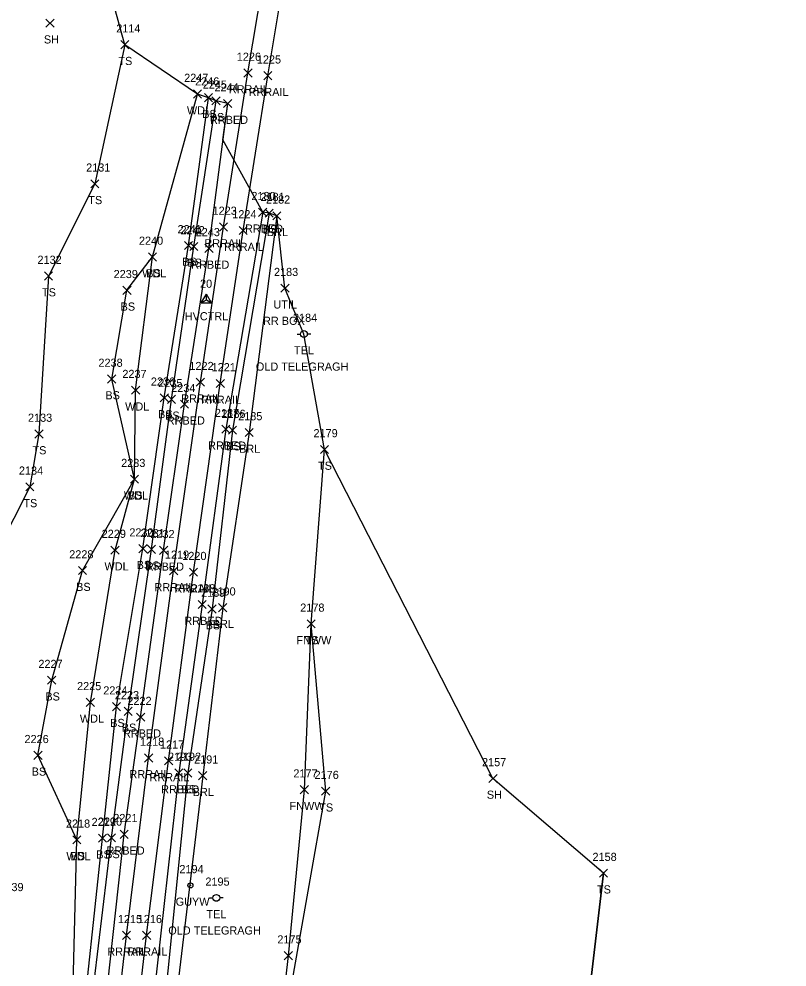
# Model space of a CAD drawing. Extents: x 1754529 to 1755810, y 621660 to 624656.
# Drawn here: x 1755616 to 1755804.8, y 623834.2 to 624067.2 of the extents above; entities that cross this region are included whole.
import ezdxf

# ---------------------------------------------------------------- set-up
doc = ezdxf.new("R2010")
doc.units = 0
for name, color, linetype in [('C_A', 7, 'Continuous'), ('C_I', 7, 'Continuous'), ('CPSM', 7, 'Continuous'), ('L_A', 7, 'Continuous'), ('L_I', 7, 'Continuous'), ('L_TIC', 7, 'Continuous'), ('LABL', 7, 'Continuous'), ('LAWA', 7, 'Continuous'), ('LELB', 7, 'Continuous'), ('LFNC', 7, 'Continuous'), ('LSOGP', 7, 'Continuous'), ('R_A', 7, 'Continuous'), ('R_I', 7, 'Continuous'), ('R_TIC', 7, 'Continuous'), ('RR', 7, 'Continuous'), ('RRB', 7, 'Continuous'), ('U_A', 7, 'Continuous'), ('U_C', 7, 'Continuous'), ('U_I', 7, 'Continuous'), ('UDEFAULT', 7, 'Continuous'), ('UP', 7, 'Continuous'), ('UPGW', 7, 'Continuous')]:
    doc.layers.add(name, color=color, linetype=linetype)

msp = doc.modelspace()

# ---------------------------------------------------------------- linework, layer by layer
at = {"layer": 'CPSM'}
for p, q in [((1755660.82, 623997.4), (1755662.07, 623999.57)), ((1755663.32, 623997.4), (1755662.07, 623999.57)), ((1755662.07, 623998.12), (1755662.07, 623999.57)), ((1755660.82, 623997.4), (1755662.07, 623998.12)), ((1755660.82, 623997.4), (1755663.32, 623997.4)), ((1755662.07, 623998.12), (1755662.07, 623998.12)), ((1755662.07, 623998.12), (1755663.32, 623997.4))]:
    msp.add_line(p, q, dxfattribs=at)
at = {"layer": 'L_TIC'}
for points in [[(1755622.67, 624065.15), (1755624.67, 624067.15)], [(1755624.67, 624065.15), (1755622.67, 624067.15)], [(1755641.06, 624059.86), (1755643.06, 624061.86)], [(1755643.06, 624059.86), (1755641.06, 624061.86)], [(1755658.88, 624047.72), (1755660.88, 624049.72)], [(1755660.88, 624047.72), (1755658.88, 624049.72)], [(1755661.62, 624046.83), (1755663.62, 624048.83)], [(1755663.62, 624046.83), (1755661.62, 624048.83)], [(1755663.45, 624046.05), (1755665.45, 624048.05)], [(1755665.45, 624046.05), (1755663.45, 624048.05)], [(1755633.66, 624025.67), (1755635.66, 624027.67)], [(1755635.66, 624025.67), (1755633.66, 624027.67)], [(1755676.5, 624018.45), (1755678.5, 624020.45)], [(1755678.5, 624018.45), (1755676.5, 624020.45)], [(1755678.41, 624017.81), (1755680.41, 624019.81)], [(1755680.41, 624017.81), (1755678.41, 624019.81)], [(1755656.7, 624010.52), (1755658.7, 624012.52)], [(1755658.7, 624010.52), (1755656.7, 624012.52)], [(1755657.98, 624010.28), (1755659.98, 624012.28)], [(1755659.98, 624010.28), (1755657.98, 624012.28)], [(1755647.86, 624007.69), (1755649.86, 624009.69)], [(1755649.86, 624007.69), (1755647.86, 624009.69)], [(1755647.86, 624007.69), (1755649.86, 624009.69)], [(1755649.86, 624007.69), (1755647.86, 624009.69)], [(1755622.28, 624003), (1755624.28, 624005)], [(1755624.28, 624003), (1755622.28, 624005)], [(1755641.56, 623999.5), (1755643.56, 624001.5)], [(1755643.56, 623999.5), (1755641.56, 624001.5)], [(1755637.82, 623977.7), (1755639.82, 623979.7)], [(1755639.82, 623977.7), (1755637.82, 623979.7)], [(1755643.69, 623974.95), (1755645.69, 623976.95)], [(1755645.69, 623974.95), (1755643.69, 623976.95)], [(1755650.75, 623973.07), (1755652.75, 623975.07)], [(1755652.75, 623973.07), (1755650.75, 623975.07)], [(1755652.51, 623972.7), (1755654.51, 623974.7)], [(1755654.51, 623972.7), (1755652.51, 623974.7)], [(1755667.5, 623965.15), (1755669.5, 623967.15)], [(1755669.5, 623965.15), (1755667.5, 623967.15)], [(1755671.58, 623964.56), (1755673.58, 623966.56)], [(1755673.58, 623964.56), (1755671.58, 623966.56)], [(1755619.94, 623964.19), (1755621.94, 623966.19)], [(1755621.94, 623964.19), (1755619.94, 623966.19)], [(1755690.1, 623960.39), (1755692.1, 623962.39)], [(1755692.1, 623960.39), (1755690.1, 623962.39)], [(1755643.4, 623953.08), (1755645.4, 623955.08)], [(1755645.4, 623953.08), (1755643.4, 623955.08)], [(1755643.4, 623953.08), (1755645.4, 623955.08)], [(1755645.4, 623953.08), (1755643.4, 623955.08)], [(1755617.71, 623951.2), (1755619.71, 623953.2)], [(1755619.71, 623951.2), (1755617.71, 623953.2)], [(1755638.63, 623935.66), (1755640.63, 623937.66)], [(1755640.63, 623935.66), (1755638.63, 623937.66)], [(1755645.5, 623936.01), (1755647.5, 623938.01)], [(1755647.5, 623936.01), (1755645.5, 623938.01)], [(1755647.59, 623935.85), (1755649.59, 623937.85)], [(1755649.59, 623935.85), (1755647.59, 623937.85)], [(1755630.64, 623930.62), (1755632.64, 623932.62)], [(1755632.64, 623930.62), (1755630.64, 623932.62)], [(1755662.47, 623921.18), (1755664.47, 623923.18)], [(1755664.47, 623921.18), (1755662.47, 623923.18)], [(1755665.1, 623921.5), (1755667.1, 623923.5)], [(1755667.1, 623921.5), (1755665.1, 623923.5)], [(1755686.83, 623917.52), (1755688.83, 623919.52)], [(1755688.83, 623917.52), (1755686.83, 623919.52)], [(1755686.83, 623917.52), (1755688.83, 623919.52)], [(1755688.83, 623917.52), (1755686.83, 623919.52)], [(1755623.07, 623903.69), (1755625.07, 623905.69)], [(1755625.07, 623903.69), (1755623.07, 623905.69)], [(1755632.57, 623898.24), (1755634.57, 623900.24)], [(1755634.57, 623898.24), (1755632.57, 623900.24)], [(1755639.01, 623897.18), (1755641.01, 623899.18)], [(1755641.01, 623897.18), (1755639.01, 623899.18)], [(1755641.85, 623896.02), (1755643.85, 623898.02)], [(1755643.85, 623896.02), (1755641.85, 623898.02)], [(1755619.7, 623885.23), (1755621.7, 623887.23)], [(1755621.7, 623885.23), (1755619.7, 623887.23)], [(1755656.52, 623880.88), (1755658.52, 623882.88)], [(1755658.52, 623880.88), (1755656.52, 623882.88)], [(1755660.18, 623880.21), (1755662.18, 623882.21)], [(1755662.18, 623880.21), (1755660.18, 623882.21)], [(1755731.5, 623879.55), (1755733.5, 623881.55)], [(1755733.5, 623879.55), (1755731.5, 623881.55)], [(1755685.15, 623876.78), (1755687.15, 623878.78)], [(1755687.15, 623876.78), (1755685.15, 623878.78)], [(1755690.4, 623876.41), (1755692.4, 623878.41)], [(1755692.4, 623876.41), (1755690.4, 623878.41)], [(1755629.26, 623864.45), (1755631.26, 623866.45)], [(1755631.26, 623864.45), (1755629.26, 623866.45)], [(1755629.26, 623864.45), (1755631.26, 623866.45)], [(1755631.26, 623864.45), (1755629.26, 623866.45)], [(1755635.58, 623864.85), (1755637.58, 623866.85)], [(1755637.58, 623864.85), (1755635.58, 623866.85)], [(1755637.78, 623864.94), (1755639.78, 623866.94)], [(1755639.78, 623864.94), (1755637.78, 623866.94)], [(1755758.64, 623856.27), (1755760.64, 623858.27)], [(1755760.64, 623856.27), (1755758.64, 623858.27)], [(1755681.22, 623835.98), (1755683.22, 623837.98)], [(1755683.22, 623835.98), (1755681.22, 623837.98)]]:
    msp.add_lwpolyline(points, dxfattribs=at)
at = {"layer": 'LABL'}
msp.add_lwpolyline([(1755679.41, 624018.81), (1755672.58, 623965.56), (1755666.1, 623922.5), (1755661.18, 623881.21), (1755654.48, 623825.24), (1755650.07, 623783.16), (1755645, 623731.12)], dxfattribs=at)
at = {"layer": 'LAWA'}
msp.add_lwpolyline([(1755619.86, 623730.16), (1755624.14, 623766.63), (1755628.98, 623813.62), (1755630.26, 623865.45), (1755633.57, 623899.24), (1755639.63, 623936.66), (1755644.4, 623954.08), (1755644.69, 623975.95), (1755648.86, 624008.69), (1755659.88, 624048.72)], dxfattribs=at)
at = {"layer": 'LELB'}
for points in [[(1755642.06, 624060.86), (1755634.66, 624026.67), (1755623.28, 624004), (1755620.94, 623965.19), (1755618.71, 623952.2), (1755606.81, 623928.84), (1755598.16, 623898.45), (1755598.5, 623876.91), (1755607.67, 623866.57), (1755613.91, 623849.85), (1755612.83, 623834.4)], [(1755621.92, 623730), (1755626.29, 623766.54), (1755630.92, 623812.95), (1755636.58, 623865.85), (1755640.01, 623898.18), (1755646.5, 623937.01), (1755651.75, 623974.07), (1755657.7, 624011.52), (1755662.62, 624047.83)], [(1755623.71, 623730.49), (1755627.77, 623766.25), (1755632.35, 623812.84), (1755638.78, 623865.94), (1755642.85, 623897.02), (1755648.59, 623936.85), (1755653.51, 623973.7), (1755658.98, 624011.28), (1755664.45, 624047.05)], [(1755677.5, 624019.45), (1755668.5, 623966.15), (1755663.47, 623922.18), (1755657.52, 623881.88), (1755651.77, 623825.19), (1755647.93, 623784.26), (1755642.72, 623732.01)], [(1755630.26, 623865.45), (1755620.7, 623886.23), (1755624.07, 623904.69), (1755631.64, 623931.62), (1755644.4, 623954.08), (1755638.82, 623978.7), (1755642.56, 624000.5), (1755648.86, 624008.69)], [(1755759.64, 623857.27), (1755754.21, 623811.35), (1755753.42, 623772.78), (1755766.33, 623740.32), (1755774.14, 623720.79), (1755758.9, 623706.26), (1755730.32, 623712.44), (1755693.64, 623709.04), (1755674.97, 623707.43), (1755670.91, 623711.42), (1755668.71, 623724.8), (1755675.07, 623772.54), (1755678.37, 623803.67), (1755691.4, 623877.41), (1755687.83, 623918.52), (1755691.1, 623961.39)]]:
    msp.add_lwpolyline(points, dxfattribs=at)
at = {"layer": 'LFNC'}
msp.add_lwpolyline([(1755678.37, 623803.67), (1755682.22, 623836.98), (1755686.15, 623877.78), (1755687.83, 623918.52)], dxfattribs=at)
at = {"layer": 'LSOGP'}
msp.add_lwpolyline([(1755754.21, 623811.35), (1755759.64, 623857.27), (1755732.5, 623880.55), (1755691.1, 623961.39), (1755686.05, 623989.75), (1755681.39, 624001.01), (1755679.41, 624018.81), (1755677.5, 624019.45), (1755675.92, 624019.67), (1755666.16, 624037.49), (1755667.32, 624046.39), (1755664.45, 624047.05), (1755662.62, 624047.83), (1755659.88, 624048.72), (1755642.06, 624060.86), (1755626.78, 624116.47)], dxfattribs=at)
at = {"layer": 'R_TIC'}
for points in [[(1755671.3, 624052.9), (1755673.3, 624054.9)], [(1755673.3, 624052.9), (1755671.3, 624054.9)], [(1755676.17, 624052.23), (1755678.17, 624054.23)], [(1755678.17, 624052.23), (1755676.17, 624054.23)], [(1755666.32, 624045.39), (1755668.32, 624047.39)], [(1755668.32, 624045.39), (1755666.32, 624047.39)], [(1755674.92, 624018.67), (1755676.92, 624020.67)], [(1755676.92, 624018.67), (1755674.92, 624020.67)], [(1755665.29, 624015.06), (1755667.29, 624017.06)], [(1755667.29, 624015.06), (1755665.29, 624017.06)], [(1755670.13, 624014.19), (1755672.13, 624016.19)], [(1755672.13, 624014.19), (1755670.13, 624016.19)], [(1755661.71, 624009.8), (1755663.71, 624011.8)], [(1755663.71, 624009.8), (1755661.71, 624011.8)], [(1755659.61, 623976.9), (1755661.61, 623978.9)], [(1755661.61, 623976.9), (1755659.61, 623978.9)], [(1755664.5, 623976.61), (1755666.5, 623978.61)], [(1755666.5, 623976.61), (1755664.5, 623978.61)], [(1755655.7, 623971.5), (1755657.7, 623973.5)], [(1755657.7, 623971.5), (1755655.7, 623973.5)], [(1755665.85, 623965.35), (1755667.85, 623967.35)], [(1755667.85, 623965.35), (1755665.85, 623967.35)], [(1755650.57, 623935.6), (1755652.57, 623937.6)], [(1755652.57, 623935.6), (1755650.57, 623937.6)], [(1755653.04, 623930.54), (1755655.04, 623932.54)], [(1755655.04, 623930.54), (1755653.04, 623932.54)], [(1755657.94, 623930.22), (1755659.94, 623932.22)], [(1755659.94, 623930.22), (1755657.94, 623932.22)], [(1755660.03, 623922.27), (1755662.03, 623924.27)], [(1755662.03, 623922.27), (1755660.03, 623924.27)], [(1755644.93, 623894.6), (1755646.93, 623896.6)], [(1755646.93, 623894.6), (1755644.93, 623896.6)], [(1755646.89, 623884.58), (1755648.89, 623886.58)], [(1755648.89, 623884.58), (1755646.89, 623886.58)], [(1755651.81, 623883.87), (1755653.81, 623885.87)], [(1755653.81, 623883.87), (1755651.81, 623885.87)], [(1755654.33, 623880.88), (1755656.33, 623882.88)], [(1755656.33, 623880.88), (1755654.33, 623882.88)], [(1755640.9, 623865.82), (1755642.9, 623867.82)], [(1755642.9, 623865.82), (1755640.9, 623867.82)], [(1755641.45, 623840.98), (1755643.45, 623842.98)], [(1755643.45, 623840.98), (1755641.45, 623842.98)], [(1755646.4, 623841), (1755648.4, 623843)], [(1755648.4, 623841), (1755646.4, 623843)]]:
    msp.add_lwpolyline(points, dxfattribs=at)
at = {"layer": 'RR'}
for points in [[(1755627.39, 623699.11), (1755631.78, 623745.19), (1755637.11, 623795.68), (1755642.45, 623841.98), (1755647.89, 623885.58), (1755654.04, 623931.54), (1755660.61, 623977.9), (1755666.29, 624016.06), (1755672.3, 624053.9), (1755679.64, 624097.76), (1755687.07, 624139.84), (1755694.5, 624180.62), (1755701.72, 624217.85), (1755709.31, 624256.23), (1755717.86, 624297.53), (1755724.56, 624328.91), (1755733.93, 624371.3), (1755743.26, 624412.4), (1755753.41, 624456.24), (1755764.06, 624501.26), (1755774.99, 624547.18), (1755787.52, 624599.52), (1755800.05, 624650.73)], [(1755632.43, 623698.79), (1755636.73, 623745.2), (1755642.03, 623795.46), (1755647.4, 623842), (1755652.81, 623884.87), (1755658.94, 623931.22), (1755665.5, 623977.61), (1755671.13, 624015.19), (1755677.17, 624053.23), (1755684.42, 624096.54), (1755692.03, 624139.27), (1755699.47, 624179.9), (1755706.47, 624216.55), (1755714.07, 624254.59), (1755722.62, 624295.88), (1755729.35, 624327.29), (1755738.69, 624369.66), (1755747.98, 624411.22), (1755758.14, 624454.7), (1755769.01, 624500.51), (1755779.76, 624545.7), (1755792.4, 624598.28), (1755804.75, 624649.74)]]:
    msp.add_lwpolyline(points, dxfattribs=at)
at = {"layer": 'RRB'}
for points in [[(1755627.02, 623730.97), (1755631.33, 623765.95), (1755635.85, 623811.52), (1755641.9, 623866.82), (1755645.93, 623895.6), (1755651.57, 623936.6), (1755656.7, 623972.5), (1755662.71, 624010.8), (1755667.32, 624046.39)], [(1755675.92, 624019.67), (1755666.85, 623966.35), (1755661.03, 623923.27), (1755655.33, 623881.88), (1755648.99, 623825.74), (1755644.79, 623784.74), (1755640.85, 623733.14)]]:
    msp.add_lwpolyline(points, dxfattribs=at)
at = {"layer": 'UDEFAULT'}
for points in [[(1755680.39, 624000.01), (1755682.39, 624002.01)], [(1755682.39, 624000.01), (1755680.39, 624002.01)]]:
    msp.add_lwpolyline(points, dxfattribs=at)
at = {"layer": 'UP'}
for p, q in [((1755684.39, 623989.75), (1755685.22, 623989.75)), ((1755686.05, 623989.75), (1755686.05, 623989.75)), ((1755687.72, 623989.75), (1755686.88, 623989.75)), ((1755686.88, 623989.75), (1755686.88, 623989.75)), ((1755687.72, 623989.75), (1755687.72, 623989.75)), ((1755662.87, 623851.18), (1755663.7, 623851.18)), ((1755664.53, 623851.19), (1755664.53, 623851.19)), ((1755666.2, 623851.19), (1755665.37, 623851.19)), ((1755665.37, 623851.19), (1755665.37, 623851.19)), ((1755666.2, 623851.19), (1755666.2, 623851.19))]:
    msp.add_line(p, q, dxfattribs=at)
for centre in [(1755686.05, 623989.75), (1755664.53, 623851.19)]:
    msp.add_circle(centre, 0.833, dxfattribs=at)
at = {"layer": 'UPGW'}
for radius in [0.625, 0.0833]:
    msp.add_circle((1755658.15, 623854.26), radius, dxfattribs=at)

# ---------------------------------------------------------------- texts
at = {"layer": 'C_A'}
msp.add_text('HVCTRL', height=2, dxfattribs=at).set_placement((1755656.76, 623993.12))
at = {"layer": 'C_I'}
msp.add_text('20', height=2, dxfattribs=at).set_placement((1755660.52, 624001.12))
at = {"layer": 'L_A'}
for s, p in [('SH', (1755622.16, 624061.15)), ('TS', (1755640.47, 624055.86)), ('WDL', (1755657.3, 624043.72)), ('BS', (1755661.06, 624042.83)), ('BS', (1755662.89, 624042.05)), ('TS', (1755633.07, 624021.67)), ('BS', (1755675.94, 624014.45)), ('BRL', (1755676.95, 624013.81)), ('BS', (1755656.14, 624006.52)), ('BS', (1755657.42, 624006.28)), ('WDL', (1755646.28, 624003.69)), ('BS', (1755647.3, 624003.69)), ('TS', (1755621.69, 623999)), ('BS', (1755641, 623995.5)), ('BS', (1755637.26, 623973.7)), ('WDL', (1755642.11, 623970.95)), ('BS', (1755650.19, 623969.07)), ('BS', (1755651.95, 623968.7)), ('TS', (1755619.35, 623960.19)), ('BS', (1755666.95, 623961.15)), ('BRL', (1755670.12, 623960.56)), ('TS', (1755689.51, 623956.39)), ('WDL', (1755641.82, 623949.08)), ('BS', (1755642.84, 623949.08)), ('TS', (1755617.12, 623947.2)), ('BS', (1755644.95, 623932.01)), ('WDL', (1755637.04, 623931.66)), ('BS', (1755647.03, 623931.85)), ('BS', (1755630.08, 623926.62)), ('BS', (1755661.91, 623917.18)), ('BRL', (1755663.65, 623917.5)), ('FNWW', (1755684.18, 623913.52)), ('TS', (1755686.24, 623913.52)), ('BS', (1755622.51, 623899.69)), ('WDL', (1755630.99, 623894.24)), ('BS', (1755638.45, 623893.18)), ('BS', (1755641.29, 623892.02)), ('BS', (1755619.15, 623881.23)), ('BS', (1755655.96, 623876.88)), ('BRL', (1755658.72, 623876.21)), ('SH', (1755730.99, 623875.55)), ('FNWW', (1755682.5, 623872.78)), ('TS', (1755689.81, 623872.41)), ('WDL', (1755627.68, 623860.45)), ('BS', (1755628.7, 623860.45)), ('BS', (1755635.02, 623860.85)), ('BS', (1755637.22, 623860.94)), ('TS', (1755758.05, 623852.27))]:
    msp.add_text(s, height=2, dxfattribs=at).set_placement(p)
at = {"layer": 'L_I'}
for s, p in [('2114', (1755639.93, 624063.86)), ('2247', (1755656.62, 624051.72)), ('2246', (1755659.31, 624050.83)), ('2245', (1755661.19, 624050.05)), ('2131', (1755632.54, 624029.67)), ('2181', (1755675.37, 624022.45)), ('2182', (1755676.72, 624021.81)), ('2241', (1755655, 624014.52)), ('2242', (1755655.72, 624014.28)), ('2240', (1755645.51, 624011.69)), ('2240', (1755645.51, 624011.69)), ('2132', (1755620.58, 624007)), ('2239', (1755639.29, 624003.5)), ('2238', (1755635.56, 623981.7)), ('2237', (1755641.43, 623978.95)), ('2236', (1755648.44, 623977.07)), ('2235', (1755650.25, 623976.7)), ('2186', (1755665.76, 623969.15)), ('2133', (1755618.25, 623968.19)), ('2185', (1755669.89, 623968.56)), ('2179', (1755688.4, 623964.39)), ('2134', (1755616.02, 623955.2)), ('2233', (1755641.14, 623957.08)), ('2233', (1755641.14, 623957.08)), ('2229', (1755636.36, 623939.66)), ('2230', (1755643.16, 623940.01)), ('2231', (1755645.89, 623939.85)), ('2228', (1755628.38, 623934.62)), ('2189', (1755660.77, 623925.18)), ('2190', (1755663.32, 623925.5)), ('2178', (1755685.14, 623921.52)), ('2178', (1755685.14, 623921.52)), ('2227', (1755620.81, 623907.69)), ('2225', (1755630.31, 623902.24)), ('2224', (1755636.75, 623901.18)), ('2223', (1755639.59, 623900.02)), ('2226', (1755617.39, 623889.23)), ('2192', (1755654.83, 623884.88)), ('2191', (1755659.06, 623884.21)), ('2157', (1755729.81, 623883.55)), ('2177', (1755683.46, 623880.78)), ('2176', (1755688.66, 623880.41)), ('2218', (1755627.57, 623868.45)), ('2218', (1755627.57, 623868.45)), ('2219', (1755633.88, 623868.85)), ('2220', (1755635.43, 623868.94)), ('2158', (1755756.95, 623860.27)), ('2139', (1755611.21, 623852.85)), ('2175', (1755679.52, 623839.98))]:
    msp.add_text(s, height=2, dxfattribs=at).set_placement(p)
at = {"layer": 'R_A'}
for s, p in [('RRRAIL', (1755667.59, 624048.9)), ('RRRAIL', (1755672.46, 624048.23)), ('RRBED', (1755662.96, 624041.39)), ('RRBED', (1755671.56, 624014.67)), ('RRRAIL', (1755661.59, 624011.06)), ('RRRAIL', (1755666.42, 624010.19)), ('RRBED', (1755658.35, 624005.8)), ('RRRAIL', (1755655.9, 623972.9)), ('RRRAIL', (1755660.79, 623972.61)), ('RRBED', (1755652.34, 623967.5)), ('RRBED', (1755662.5, 623961.35)), ('RRBED', (1755647.22, 623931.6)), ('RRRAIL', (1755649.33, 623926.54)), ('RRRAIL', (1755654.23, 623926.22)), ('RRBED', (1755656.68, 623918.27)), ('RRBED', (1755641.58, 623890.6)), ('RRRAIL', (1755643.18, 623880.58)), ('RRRAIL', (1755648.1, 623879.87)), ('RRBED', (1755650.97, 623876.88)), ('RRBED', (1755637.55, 623861.82)), ('RRRAIL', (1755637.74, 623836.98)), ('RRRAIL', (1755642.69, 623837))]:
    msp.add_text(s, height=2, dxfattribs=at).set_placement(p)
at = {"layer": 'R_I'}
for s, p in [('1226', (1755669.55, 624056.9)), ('1225', (1755674.48, 624056.23)), ('2244', (1755664.06, 624049.39)), ('2180', (1755673.14, 624022.67)), ('1223', (1755663.6, 624019.06)), ('1224', (1755668.44, 624018.19)), ('2243', (1755659.45, 624013.8)), ('1222', (1755657.91, 623980.9)), ('1221', (1755663.37, 623980.61)), ('2234', (1755653.44, 623975.5)), ('2187', (1755664.16, 623969.35)), ('2232', (1755648.31, 623939.6)), ('1219', (1755651.9, 623934.54)), ('1220', (1755656.16, 623934.22)), ('2188', (1755658.34, 623926.27)), ('2222', (1755642.67, 623898.6)), ('1218', (1755645.77, 623888.58)), ('1217', (1755650.68, 623887.87)), ('2193', (1755652.64, 623884.88)), ('2221', (1755639.21, 623869.82)), ('1215', (1755640.33, 623844.98)), ('1216', (1755645.22, 623845))]:
    msp.add_text(s, height=2, dxfattribs=at).set_placement(p)
at = {"layer": 'U_A'}
for s, p in [('UTIL', (1755678.55, 623996.01)), ('TEL', (1755683.61, 623984.75)), ('GUYW', (1755654.54, 623849.26)), ('TEL', (1755662.09, 623846.19))]:
    msp.add_text(s, height=2, dxfattribs=at).set_placement(p)
at = {"layer": 'U_C'}
for s, p in [('RR BOX', (1755676, 623992.01)), ('OLD TELEGRAGH', (1755674.24, 623980.75)), ('OLD TELEGRAGH', (1755652.72, 623842.19))]:
    msp.add_text(s, height=2, dxfattribs=at).set_placement(p)
at = {"layer": 'U_I'}
for s, p in [('2183', (1755678.69, 624004.01)), ('2184', (1755683.36, 623992.75)), ('2194', (1755655.45, 623857.26)), ('2195', (1755661.84, 623854.19))]:
    msp.add_text(s, height=2, dxfattribs=at).set_placement(p)

doc.saveas('drawing.dxf')
